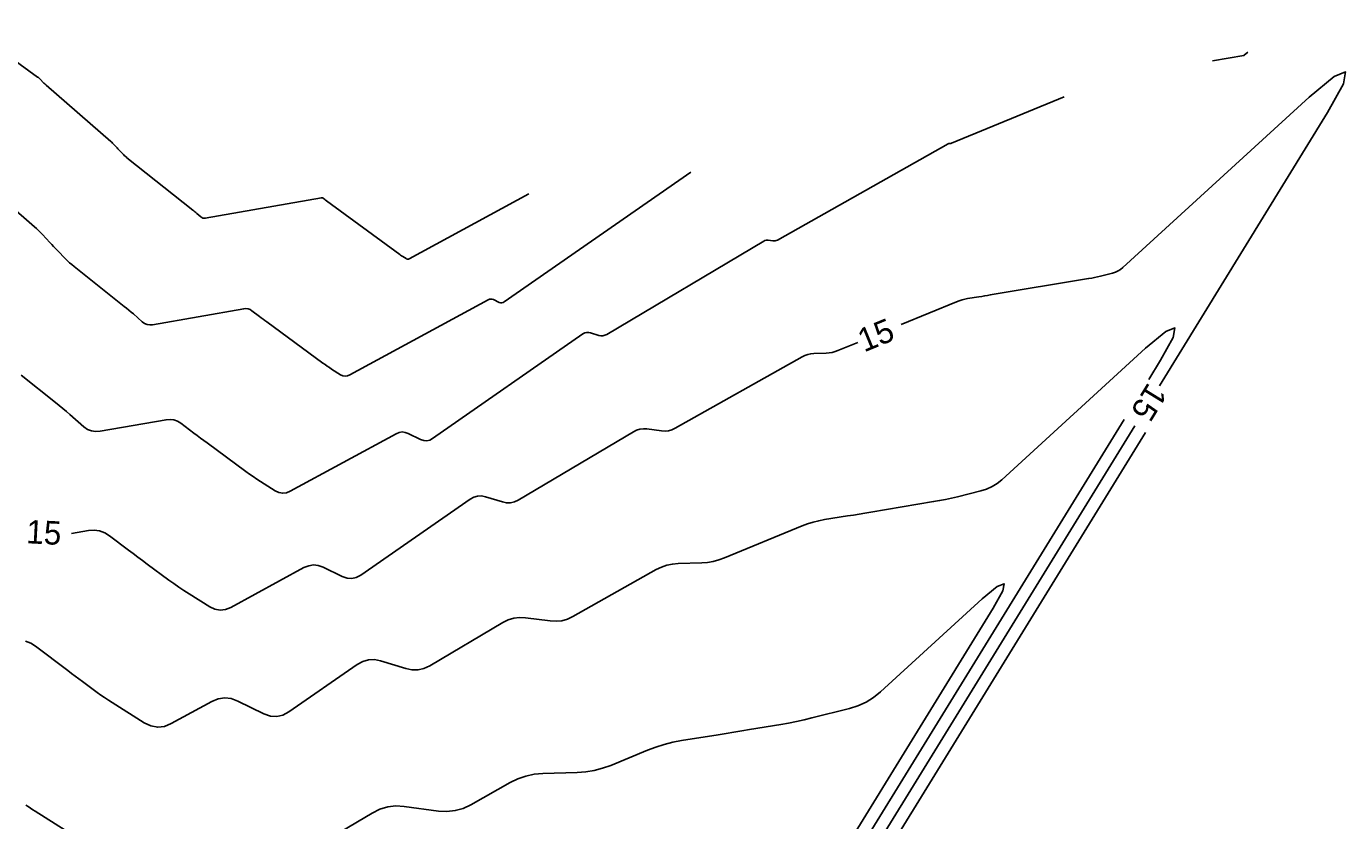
# Model space of a CAD drawing. Extents: x 1797789 to 1803805, y 249066 to 250293.
# Drawn here: x 1798416.4 to 1798753.1, y 249930.5 to 250133.2 of the extents above; entities that cross this region are included whole.
import ezdxf

# ---------------------------------------------------------------- set-up
doc = ezdxf.new("R2010")
doc.units = 0
doc.layers.add('33', color=7, linetype='Continuous')
doc.layers.add('34', color=7, linetype='Continuous')

msp = doc.modelspace()

# ---------------------------------------------------------------- linework, layer by layer
at = {"layer": '33'}
for points in [[(1798639.69, 250057.11), (1798653.82, 250062.92), (1798654.51, 250063.18), (1798655.2, 250063.4), (1798655.9, 250063.58), (1798656.62, 250063.71), (1798659.51, 250064.18), (1798660.23, 250064.29), (1798660.96, 250064.41), (1798661.68, 250064.53), (1798662.4, 250064.65), (1798687.52, 250068.84), (1798688.29, 250068.98), (1798689.05, 250069.13), (1798689.81, 250069.29), (1798690.57, 250069.48), (1798693.6, 250070.23), (1798694.34, 250070.46), (1798695.03, 250070.78), (1798695.67, 250071.18), (1798696.27, 250071.67), (1798743.8, 250115.12), (1798750.18, 250120.43), (1798753.09, 250121.56), (1798752.53, 250118.49), (1798748.51, 250111.22), (1798705.57, 250041.44)], [(1798427.94, 250003.75), (1798432.3, 250004.52), (1798433.75, 250004.63), (1798435.12, 250004.45), (1798436.43, 250003.98), (1798437.66, 250003.22), (1798442.46, 249999.57), (1798443.66, 249998.66), (1798444.87, 249997.76), (1798446.08, 249996.86), (1798447.29, 249995.97), (1798452.82, 249991.91), (1798454.08, 249991), (1798455.36, 249990.12), (1798456.65, 249989.25), (1798457.96, 249988.41), (1798463.23, 249985.09), (1798464.55, 249984.46), (1798465.89, 249984.22), (1798467.24, 249984.37), (1798468.6, 249984.92), (1798487.27, 249995.07), (1798488.48, 249995.57), (1798489.69, 249995.75), (1798490.91, 249995.62), (1798492.13, 249995.18), (1798497.06, 249992.78), (1798498.27, 249992.35), (1798499.46, 249992.27), (1798500.63, 249992.53), (1798501.76, 249993.14), (1798529.66, 250012.54), (1798530.6, 250013.06), (1798531.57, 250013.33), (1798532.58, 250013.36), (1798533.63, 250013.15), (1798537.9, 250011.83), (1798538.95, 250011.61), (1798539.98, 250011.62), (1798540.98, 250011.85), (1798541.96, 250012.31), (1798571.34, 250029.75), (1798572.16, 250030.15), (1798573.01, 250030.4), (1798573.89, 250030.51), (1798574.8, 250030.46), (1798578.51, 250029.96), (1798579.43, 250029.91), (1798580.31, 250030), (1798581.17, 250030.24), (1798582, 250030.63), (1798614.42, 250048.9), (1798615.12, 250049.24), (1798615.84, 250049.49), (1798616.59, 250049.65), (1798617.37, 250049.72), (1798620.52, 250049.82), (1798621.3, 250049.88), (1798622.06, 250050), (1798622.81, 250050.2), (1798623.55, 250050.47), (1798628.59, 250052.54)], [(1798699.28, 250031.22), (1798579.8, 249837.04)]]:
    msp.add_lwpolyline(points, dxfattribs=at)
at = {"layer": '34'}
for points in [[(1798544.66, 250090.49), (1798514.15, 250073.89), (1798513.94, 250073.81), (1798513.74, 250073.79), (1798513.53, 250073.83), (1798513.33, 250073.92), (1798512.53, 250074.43), (1798512.33, 250074.55), (1798512.14, 250074.68), (1798511.94, 250074.82), (1798511.75, 250074.96), (1798493.02, 250088.7), (1798492.92, 250088.78), (1798492.81, 250088.86), (1798492.7, 250088.94), (1798492.6, 250089.02), (1798492.18, 250089.34), (1798492.07, 250089.4), (1798491.96, 250089.44), (1798491.84, 250089.46), (1798491.71, 250089.45), (1798462.08, 250084.25), (1798461.77, 250084.22), (1798461.47, 250084.27), (1798461.19, 250084.39), (1798460.93, 250084.57), (1798459.93, 250085.45), (1798459.68, 250085.66), (1798459.43, 250085.88), (1798459.17, 250086.09), (1798458.91, 250086.3), (1798442.1, 250099.68), (1798441.87, 250099.87), (1798441.65, 250100.07), (1798441.43, 250100.27), (1798441.22, 250100.48), (1798440.37, 250101.34), (1798440.17, 250101.54), (1798439.97, 250101.75), (1798439.78, 250101.96), (1798439.58, 250102.16), (1798438.82, 250103), (1798438.62, 250103.21), (1798438.42, 250103.41), (1798438.21, 250103.61), (1798438, 250103.8), (1798421.48, 250118.15), (1798421.29, 250118.32), (1798421.11, 250118.49), (1798420.93, 250118.67), (1798420.75, 250118.86), (1798420.06, 250119.6), (1798419.89, 250119.78), (1798419.7, 250119.96), (1798419.51, 250120.12), (1798419.31, 250120.27), (1798401.51, 250133.19)], [(1798719.12, 250124.44), (1798727.1, 250125.77), (1798727.11, 250125.78), (1798727.12, 250125.78), (1798727.13, 250125.78), (1798727.13, 250125.78), (1798727.17, 250125.79), (1798727.18, 250125.79), (1798727.19, 250125.8), (1798727.2, 250125.8), (1798727.21, 250125.81), (1798728.11, 250126.64)], [(1798681.31, 250115.22), (1798652.55, 250103.39), (1798652.48, 250103.36), (1798652.4, 250103.34), (1798652.33, 250103.33), (1798652.26, 250103.33), (1798651.96, 250103.32), (1798651.88, 250103.31), (1798651.81, 250103.3), (1798651.74, 250103.27), (1798651.68, 250103.24), (1798608.08, 250078.68), (1798607.81, 250078.55), (1798607.54, 250078.47), (1798607.25, 250078.44), (1798606.96, 250078.46), (1798605.77, 250078.62), (1798605.47, 250078.63), (1798605.19, 250078.6), (1798604.92, 250078.52), (1798604.65, 250078.39), (1798564.55, 250054.59), (1798564.07, 250054.36), (1798563.57, 250054.24), (1798563.06, 250054.24), (1798562.54, 250054.35), (1798560.43, 250055.01), (1798559.91, 250055.11), (1798559.41, 250055.09), (1798558.92, 250054.96), (1798558.46, 250054.7), (1798520.08, 250028.01), (1798519.35, 250027.62), (1798518.6, 250027.45), (1798517.83, 250027.5), (1798517.05, 250027.78), (1798513.89, 250029.32), (1798513.1, 250029.6), (1798512.32, 250029.69), (1798511.54, 250029.57), (1798510.76, 250029.25), (1798483.78, 250014.58), (1798482.8, 250014.18), (1798481.84, 250014.07), (1798480.88, 250014.25), (1798479.93, 250014.7), (1798476.15, 250017.08), (1798475.21, 250017.69), (1798474.28, 250018.31), (1798473.37, 250018.94), (1798472.46, 250019.59), (1798462.53, 250026.88), (1798461.69, 250027.5), (1798460.85, 250028.13), (1798460.01, 250028.76), (1798459.17, 250029.39), (1798455.84, 250031.92), (1798454.98, 250032.45), (1798454.07, 250032.78), (1798453.11, 250032.91), (1798452.1, 250032.83), (1798435.24, 250029.87), (1798434.1, 250029.78), (1798433.03, 250029.95), (1798432.04, 250030.36), (1798431.11, 250031.02), (1798427.54, 250034.15), (1798426.64, 250034.93), (1798425.73, 250035.7), (1798424.82, 250036.45), (1798423.89, 250037.2), (1798415.09, 250044.21)], [(1798585.98, 250095.97), (1798538.39, 250062.88), (1798538.07, 250062.7), (1798537.74, 250062.63), (1798537.4, 250062.65), (1798537.05, 250062.77), (1798535.64, 250063.46), (1798535.29, 250063.58), (1798534.95, 250063.62), (1798534.6, 250063.57), (1798534.26, 250063.43), (1798498.97, 250044.24), (1798498.37, 250044), (1798497.79, 250043.93), (1798497.21, 250044.04), (1798496.63, 250044.31), (1798494.34, 250045.75), (1798493.77, 250046.12), (1798493.21, 250046.5), (1798492.66, 250046.88), (1798492.11, 250047.28), (1798477.78, 250057.79), (1798477.3, 250058.14), (1798476.83, 250058.49), (1798476.36, 250058.85), (1798475.89, 250059.2), (1798474.01, 250060.63), (1798473.52, 250060.93), (1798473.01, 250061.11), (1798472.47, 250061.18), (1798471.91, 250061.14), (1798448.66, 250057.06), (1798447.93, 250057), (1798447.25, 250057.11), (1798446.61, 250057.37), (1798446.02, 250057.8), (1798443.73, 250059.8), (1798443.16, 250060.3), (1798442.58, 250060.79), (1798441.99, 250061.27), (1798441.4, 250061.75), (1798428.59, 250071.95), (1798428.03, 250072.41), (1798427.48, 250072.89), (1798426.95, 250073.38), (1798426.43, 250073.89), (1798424.34, 250076.01), (1798423.85, 250076.51), (1798423.37, 250077.02), (1798422.89, 250077.53), (1798422.42, 250078.04), (1798420.53, 250080.1), (1798420.05, 250080.61), (1798419.55, 250081.1), (1798419.05, 250081.58), (1798418.52, 250082.05), (1798405.69, 250093.19)], [(1798416.22, 249976.29), (1798417.54, 249975.82), (1798418.79, 249975.04), (1798427.02, 249968.79), (1798427.95, 249968.09), (1798428.88, 249967.39), (1798429.82, 249966.7), (1798430.76, 249966), (1798434.51, 249963.25), (1798435.46, 249962.57), (1798436.41, 249961.9), (1798437.38, 249961.25), (1798438.36, 249960.62), (1798446.53, 249955.48), (1798448.22, 249954.67), (1798449.94, 249954.36), (1798451.67, 249954.55), (1798453.41, 249955.26), (1798463.78, 249960.89), (1798465.41, 249961.57), (1798467.06, 249961.82), (1798468.71, 249961.64), (1798470.38, 249961.04), (1798477.06, 249957.78), (1798478.71, 249957.2), (1798480.33, 249957.09), (1798481.91, 249957.45), (1798483.45, 249958.27), (1798500.86, 249970.38), (1798502.27, 249971.16), (1798503.73, 249971.57), (1798505.26, 249971.62), (1798506.83, 249971.3), (1798513.26, 249969.31), (1798514.84, 249968.98), (1798516.39, 249968.99), (1798517.89, 249969.34), (1798519.36, 249970.03), (1798538.02, 249981.11), (1798539.4, 249981.78), (1798540.83, 249982.21), (1798542.3, 249982.38), (1798543.84, 249982.29), (1798550.06, 249981.46), (1798551.6, 249981.38), (1798553.08, 249981.53), (1798554.52, 249981.94), (1798555.91, 249982.59), (1798577.17, 249994.56), (1798578.5, 249995.21), (1798579.88, 249995.69), (1798581.3, 249995.99), (1798582.78, 249996.13), (1798588.77, 249996.31), (1798590.26, 249996.42), (1798591.72, 249996.67), (1798593.15, 249997.04), (1798594.55, 249997.54), (1798614.38, 250005.71), (1798615.78, 250006.23), (1798617.2, 250006.68), (1798618.64, 250007.04), (1798620.1, 250007.32), (1798626.01, 250008.27), (1798627.49, 250008.5), (1798628.97, 250008.74), (1798630.44, 250008.99), (1798631.92, 250009.23), (1798647.94, 250011.91), (1798649.47, 250012.18), (1798650.99, 250012.48), (1798652.5, 250012.81), (1798654.01, 250013.17), (1798660.03, 250014.67), (1798661.49, 250015.13), (1798662.86, 250015.76), (1798664.14, 250016.56), (1798665.33, 250017.52), (1798702.06, 250051.1), (1798707.18, 250055.36), (1798709.51, 250056.26), (1798709.06, 250053.8), (1798705.84, 250047.98), (1798702.85, 250043.12)], [(1798696.56, 250032.9), (1798577.08, 249838.71)], [(1798702.01, 250029.55), (1798582.53, 249835.36)], [(1798548.66, 249798.63), (1798663.16, 249984.74), (1798665.59, 249989.12), (1798665.93, 249990.97), (1798664.17, 249990.29), (1798660.33, 249987.08), (1798634.39, 249963.38), (1798632.61, 249961.93), (1798630.7, 249960.74), (1798628.65, 249959.8), (1798626.46, 249959.12), (1798616.87, 249956.72), (1798614.91, 249956.25), (1798612.93, 249955.81), (1798610.95, 249955.42), (1798608.95, 249955.07), (1798600.97, 249953.74), (1798598.97, 249953.4), (1798596.97, 249953.08), (1798594.98, 249952.75), (1798592.98, 249952.43), (1798583.59, 249950.92), (1798581.37, 249950.5), (1798579.2, 249949.96), (1798577.05, 249949.29), (1798574.95, 249948.49), (1798565.55, 249944.62), (1798563.48, 249943.88), (1798561.37, 249943.33), (1798559.22, 249942.97), (1798557.03, 249942.8), (1798548.19, 249942.53), (1798546.01, 249942.34), (1798543.91, 249941.89), (1798541.87, 249941.18), (1798539.91, 249940.22), (1798529.83, 249934.54), (1798527.88, 249933.63), (1798525.86, 249933.07), (1798523.77, 249932.84), (1798521.62, 249932.96), (1798512.87, 249934.13), (1798510.72, 249934.25), (1798508.64, 249934.01), (1798506.64, 249933.41), (1798504.7, 249932.46), (1798496.77, 249927.75)], [(1798431.43, 249924.86), (1798418.65, 249932.91), (1798418.06, 249933.29), (1798417.47, 249933.69), (1798416.89, 249934.09), (1798416.32, 249934.5)]]:
    msp.add_lwpolyline(points, dxfattribs=at)

# ---------------------------------------------------------------- texts
at = {"layer": '33'}
for rotation, p in [(22.3654, (1798630.2, 250049.96)), (238.3964, (1798702.75, 250042.58)), (357.0362, (1798416.3, 250001.31))]:
    msp.add_text('15', height=6, rotation=rotation, dxfattribs=at).set_placement(p)

doc.saveas('drawing.dxf')
